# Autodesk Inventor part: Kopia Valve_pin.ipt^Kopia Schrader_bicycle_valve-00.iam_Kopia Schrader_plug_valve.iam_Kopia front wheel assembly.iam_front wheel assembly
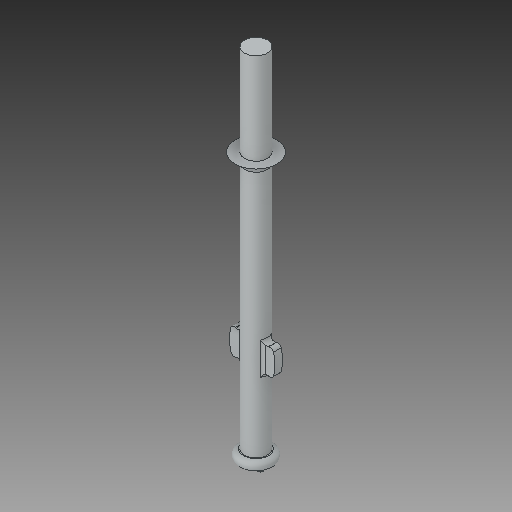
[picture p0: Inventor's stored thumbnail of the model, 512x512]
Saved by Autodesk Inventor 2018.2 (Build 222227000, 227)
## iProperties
Created: 2017-09
Part Number: Kopia Valve_pin.ipt^Kopia Schrader_bicycle_valve-00.iam_Kopia Schrader_plug_valve.iam_Kopia front wheel assembly.iam_front wheel assembly
Material: Ogólny
Document SubType Name: Modeling
Designer: Tomasz
Density: 1 g/cm^3
Appearance: Domyślna
Author: Tomasz
Sending System: SolidWorks 2017
Last Author: Tomasz
Last Saved: 2017-09-11
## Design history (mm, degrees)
feature "Valve_pin.ipt"
node "Bryła1"
